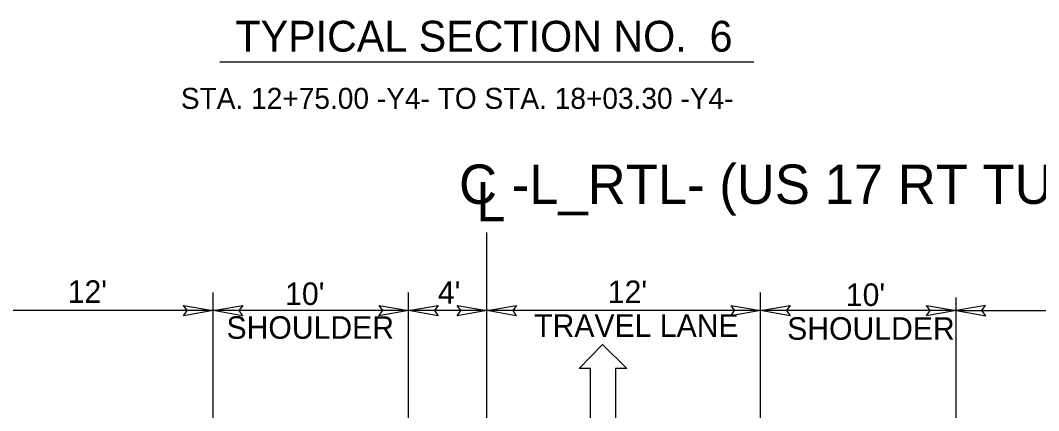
# Model space of a CAD drawing. Extents: x 2176156 to 2177167, y 76401 to 76644.
# Drawn here: x 2176797.7 to 2176849.7, y 76489.9 to 76509.8 of the extents above; entities that cross this region are included whole.
import ezdxf

# ---------------------------------------------------------------- set-up
doc = ezdxf.new("R2010")
doc.units = 0
for name, color, linetype in [('Exist Building Metal Canopy', 7, 'Continuous'), ('Exist Structure Minor Culvert Topo', 7, 'Continuous'), ('Exist Structure Minor Drop Inlet', 7, 'Continuous'), ('Exist Vegetation Woods Line', 7, 'Continuous'), ('Model Boundary Lines Text', 7, 'Continuous'), ('Old_Level_1', 7, 'Continuous'), ('Old_Level_3', 7, 'Continuous')]:
    doc.layers.add(name, color=color, linetype=linetype)

msp = doc.modelspace()

# ---------------------------------------------------------------- linework, layer by layer
at = {"layer": 'Exist Structure Minor Drop Inlet'}
for p, q in [((2176826.235, 76492.037), (2176827.438, 76493.259)), ((2176827.438, 76493.259), (2176828.68, 76492.037)), ((2176826.817, 76492.037), (2176826.235, 76492.037)), ((2176826.817, 76486.605), (2176826.817, 76492.037)), ((2176828.68, 76492.037), (2176828.098, 76492.037)), ((2176828.098, 76492.037), (2176828.098, 76486.605))]:
    msp.add_line(p, q, dxfattribs=at)
at = {"layer": 'Model Boundary Lines Text'}
msp.add_line((2176807.858, 76507.717), (2176835.179, 76507.717), dxfattribs=at)
at = {"layer": 'Old_Level_1'}
for points in [[(2176806.009, 76495.252), (2176807.519, 76494.992), (2176806.001, 76494.724), (2176806.194, 76494.992)], [(2176809.028, 76494.732), (2176807.519, 76494.992), (2176809.037, 76495.261), (2176808.844, 76494.992)], [(2176816.009, 76495.252), (2176817.519, 76494.992), (2176816.001, 76494.724), (2176816.194, 76494.992)], [(2176819.028, 76494.732), (2176817.519, 76494.992), (2176819.037, 76495.261), (2176818.844, 76494.992)], [(2176820.009, 76495.252), (2176821.519, 76494.992), (2176820.001, 76494.724), (2176820.194, 76494.992)], [(2176823.028, 76494.732), (2176821.519, 76494.992), (2176823.037, 76495.261), (2176822.844, 76494.992)], [(2176834.009, 76495.252), (2176835.519, 76494.992), (2176834.001, 76494.724), (2176834.194, 76494.992)], [(2176837.028, 76494.732), (2176835.519, 76494.992), (2176837.037, 76495.261), (2176836.844, 76494.992)], [(2176844.009, 76495.252), (2176845.519, 76494.992), (2176844.001, 76494.724), (2176844.194, 76494.992)], [(2176847.028, 76495.252), (2176845.519, 76494.992), (2176847.037, 76494.724), (2176846.844, 76494.992)]]:
    msp.add_lwpolyline(points, close=True, dxfattribs=at)
at = {"layer": 'Old_Level_3'}
for p, q in [((2176821.519, 76474.504), (2176821.519, 76498.995)), ((2176807.519, 76479.178), (2176807.519, 76495.92)), ((2176817.519, 76479.879), (2176817.519, 76495.92)), ((2176835.519, 76479.778), (2176835.519, 76495.92)), ((2176845.519, 76478.947), (2176845.519, 76495.67)), ((2176807.519, 76494.992), (2176795.519, 76494.992)), ((2176821.519, 76494.992), (2176807.519, 76494.992)), ((2176835.519, 76494.992), (2176821.519, 76494.992)), ((2176845.519, 76494.992), (2176835.519, 76494.992)), ((2176845.519, 76494.992), (2176857.519, 76494.992))]:
    msp.add_line(p, q, dxfattribs=at)

# ---------------------------------------------------------------- texts
at = {"layer": 'Exist Building Metal Canopy'}
msp.add_text('TYPICAL SECTION NO.  6', height=1.5766, rotation=0, dxfattribs=at).set_placement((2176808.664, 76508.245))
at = {"layer": 'Exist Structure Minor Culvert Topo'}
for s, height, p in [("12' ", 1.1533, (2176800.083, 76495.388)), ("4'", 1.1533, (2176819.016, 76495.341)), ("12'", 1.1533, (2176827.709, 76495.379)), ("10' ", 1.1533, (2176811.206, 76495.281)), ("10' ", 1.1533, (2176839.883, 76495.23)), ('SHOULDER', 1.1533, (2176808.205, 76493.551)), ('TRAVEL LANE', 1.15334, (2176823.94, 76493.649)), ('SHOULDER', 1.1533, (2176836.881, 76493.5))]:
    msp.add_text(s, height=height, dxfattribs=at).set_placement(p)
at = {"layer": 'Exist Vegetation Woods Line'}
for s, height, p in [('STA. 12+75.00 -Y4- TO STA. 18+03.30 -Y4-', 1.0742, (2176805.871, 76505.318)), ('C -L_RTL- (US 17 RT TURN LANE)', 2.01314, (2176820.098, 76500.455))]:
    msp.add_text(s, height=height, dxfattribs=at).set_placement(p)
msp.add_text('L', height=2.013, rotation=359.9469, dxfattribs=at).set_placement((2176820.976, 76499.554))

doc.saveas('drawing.dxf')
